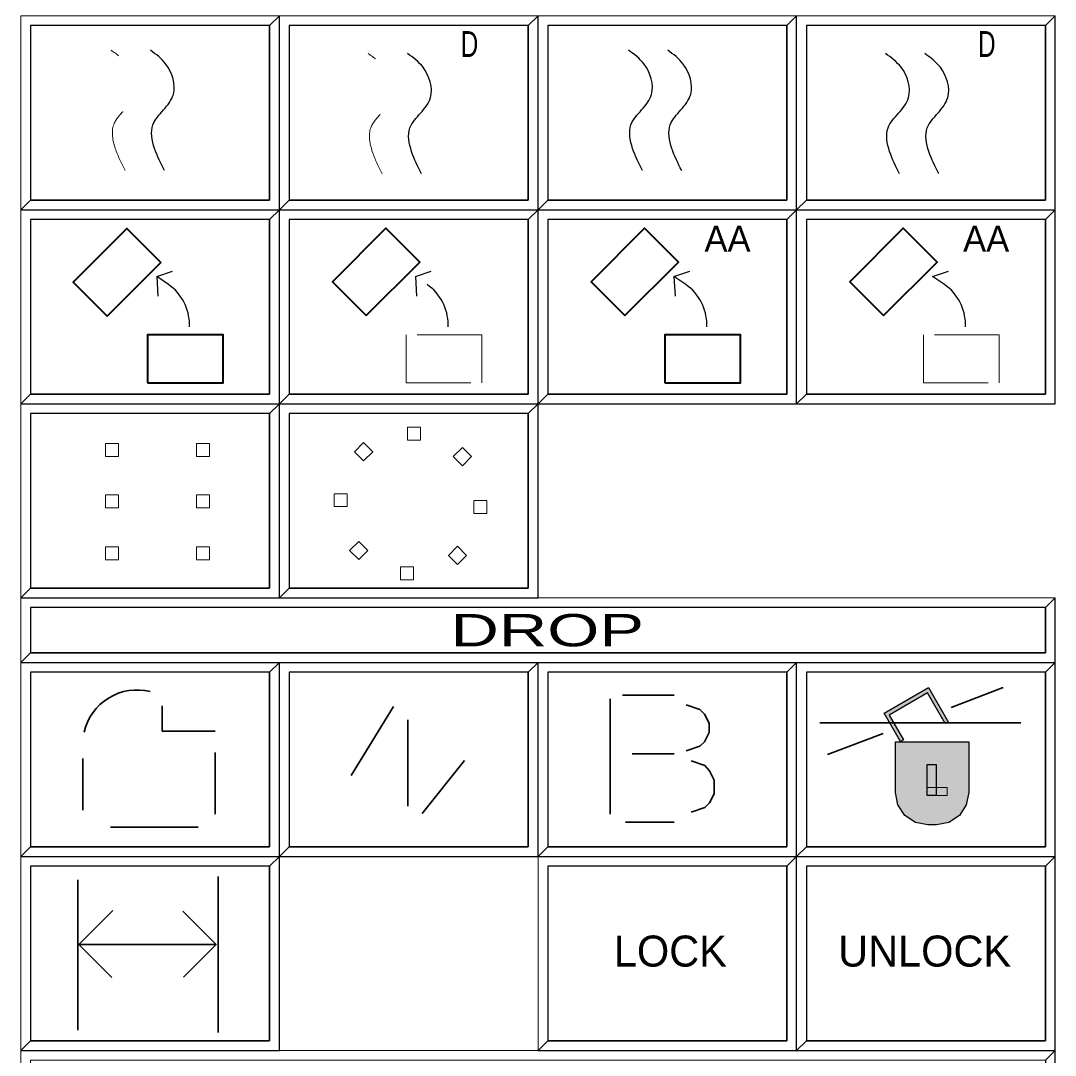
# Model space of a CAD drawing. Extents: x 95906.8 to 95923.6, y 90964.8 to 90972.8.
# Drawn here: x 95912.632 to 95914.232, y 90966.254 to 90967.854 of the extents above; entities that cross this region are included whole.
import ezdxf
from ezdxf.enums import TextEntityAlignment as Align

# ---------------------------------------------------------------- set-up
doc = ezdxf.new("R2010")
doc.units = 0
doc.header["$LTSCALE"] = 0.019
doc.linetypes.add('MEDIUM_DASHED', pattern=[4.5, 3, -1.5])
for name, color, linetype, lineweight in [('11', 7, 'Continuous', 25), ('12', 7, 'Continuous', 25), ('18', 7, 'Continuous', 25), ('2', 7, 'Continuous', 13), ('3', 7, 'Continuous', 25), ('6', 7, 'Continuous', 25), ('7', 7, 'Continuous', 35)]:
    doc.layers.add(name, color=color, linetype=linetype, lineweight=lineweight)

msp = doc.modelspace()

# ---------------------------------------------------------------- hatches: boundary and pattern name
at = {"layer": '6'}
for points in [[(95913.9928, 90966.7395), (95913.9675, 90966.7833), (95914.0361, 90966.8229), (95914.0668, 90966.7698), (95914.0621, 90966.7671), (95914.0349, 90966.8145), (95913.9753, 90966.7803), (95913.9973, 90966.7421)], [(95913.985, 90966.6604), (95913.985, 90966.7388), (95914.0985, 90966.7388), (95914.0985, 90966.6604), (95914.0947, 90966.6413), (95914.0839, 90966.625), (95914.0676, 90966.6142), (95914.0485, 90966.6104), (95914.035, 90966.6104), (95914.0159, 90966.6142), (95913.9996, 90966.625), (95913.9888, 90966.6413)], [(95914.034, 90966.7039), (95914.0482, 90966.7039), (95914.0482, 90966.6558), (95914.034, 90966.6558)], [(95914.034, 90966.6558), (95914.0653, 90966.6558), (95914.0653, 90966.6683), (95914.034, 90966.6683)]]:
    msp.add_hatch(color=256, dxfattribs=at).paths.add_polyline_path(points)

# ---------------------------------------------------------------- linework, layer by layer
at = {"layer": '11'}
for points in [[(95912.6473, 90967.5767), (95913.0173, 90967.5767), (95913.0173, 90967.8467), (95912.6473, 90967.8467)], [(95913.0473, 90967.5767), (95913.4173, 90967.5767), (95913.4173, 90967.8467), (95913.0473, 90967.8467)], [(95913.4473, 90967.5767), (95913.8173, 90967.5767), (95913.8173, 90967.8467), (95913.4473, 90967.8467)], [(95913.8473, 90967.5767), (95914.2173, 90967.5767), (95914.2173, 90967.8467), (95913.8473, 90967.8467)], [(95912.6473, 90967.2767), (95913.0173, 90967.2767), (95913.0173, 90967.5467), (95912.6473, 90967.5467)], [(95913.0473, 90967.2767), (95913.4173, 90967.2767), (95913.4173, 90967.5467), (95913.0473, 90967.5467)], [(95913.4473, 90967.2767), (95913.8173, 90967.2767), (95913.8173, 90967.5467), (95913.4473, 90967.5467)], [(95913.8473, 90967.2767), (95914.2173, 90967.2767), (95914.2173, 90967.5467), (95913.8473, 90967.5467)], [(95912.6473, 90966.9767), (95913.0173, 90966.9767), (95913.0173, 90967.2467), (95912.6473, 90967.2467)], [(95913.0473, 90966.9767), (95913.4173, 90966.9767), (95913.4173, 90967.2467), (95913.0473, 90967.2467)], [(95913.0473, 90966.5767), (95913.4173, 90966.5767), (95913.4173, 90966.8467), (95913.0473, 90966.8467)], [(95913.4473, 90966.5767), (95913.8173, 90966.5767), (95913.8173, 90966.8467), (95913.4473, 90966.8467)], [(95913.8473, 90966.5767), (95914.2173, 90966.5767), (95914.2173, 90966.8467), (95913.8473, 90966.8467)], [(95912.6473, 90966.2767), (95913.0173, 90966.2767), (95913.0173, 90966.5467), (95912.6473, 90966.5467)], [(95913.4473, 90966.2767), (95913.8173, 90966.2767), (95913.8173, 90966.5467), (95913.4473, 90966.5467)], [(95913.8473, 90966.2767), (95914.2173, 90966.2767), (95914.2173, 90966.5467), (95913.8473, 90966.5467)]]:
    msp.add_lwpolyline(points, close=True, dxfattribs=at)
at = {"layer": '12'}
msp.add_lwpolyline([(95912.6473, 90966.5767), (95913.0173, 90966.5767), (95913.0173, 90966.8467), (95912.6473, 90966.8467)], close=True, dxfattribs=at)
at = {"layer": '18'}
msp.add_lwpolyline([(95912.6473, 90966.8767), (95914.2173, 90966.8767), (95914.2173, 90966.9467), (95912.6473, 90966.9467)], close=True, dxfattribs=at)
at = {"layer": '2'}
for points in [[(95912.6323, 90967.8617), (95912.6323, 90967.5617), (95912.6473, 90967.5767), (95912.6473, 90967.8467), (95913.0173, 90967.8467), (95913.0323, 90967.8617)], [(95913.0323, 90967.8617), (95913.0323, 90967.5617), (95913.0473, 90967.5767), (95913.0473, 90967.8467), (95913.4173, 90967.8467), (95913.4323, 90967.8617)], [(95913.4323, 90967.8617), (95913.4323, 90967.5617), (95913.4473, 90967.5767), (95913.4473, 90967.8467), (95913.8173, 90967.8467), (95913.8323, 90967.8617)], [(95913.8323, 90967.8617), (95913.8323, 90967.5617), (95913.8473, 90967.5767), (95913.8473, 90967.8467), (95914.2173, 90967.8467), (95914.2323, 90967.8617)], [(95912.6323, 90967.5617), (95912.6323, 90967.2617), (95912.6473, 90967.2767), (95912.6473, 90967.5467), (95913.0173, 90967.5467), (95913.0323, 90967.5617)], [(95913.0323, 90967.5617), (95913.0323, 90967.2617), (95913.0473, 90967.2767), (95913.0473, 90967.5467), (95913.4173, 90967.5467), (95913.4323, 90967.5617)], [(95913.4323, 90967.5617), (95913.4323, 90967.2617), (95913.4473, 90967.2767), (95913.4473, 90967.5467), (95913.8173, 90967.5467), (95913.8323, 90967.5617)], [(95913.8323, 90967.5617), (95913.8323, 90967.2617), (95913.8473, 90967.2767), (95913.8473, 90967.5467), (95914.2173, 90967.5467), (95914.2323, 90967.5617)], [(95912.6323, 90967.2617), (95912.6323, 90966.9617), (95912.6473, 90966.9767), (95912.6473, 90967.2467), (95913.0173, 90967.2467), (95913.0323, 90967.2617)], [(95913.0323, 90967.2617), (95913.0323, 90966.9617), (95913.0473, 90966.9767), (95913.0473, 90967.2467), (95913.4173, 90967.2467), (95913.4323, 90967.2617)], [(95912.6323, 90966.9617), (95912.6323, 90966.8617), (95912.6473, 90966.8767), (95912.6473, 90966.9467), (95914.2173, 90966.9467), (95914.2323, 90966.9617)], [(95912.6323, 90966.8617), (95912.6323, 90966.5617), (95912.6473, 90966.5767), (95912.6473, 90966.8467), (95913.0173, 90966.8467), (95913.0323, 90966.8617)], [(95913.0323, 90966.8617), (95913.0323, 90966.5617), (95913.0473, 90966.5767), (95913.0473, 90966.8467), (95913.4173, 90966.8467), (95913.4323, 90966.8617)], [(95913.4323, 90966.8617), (95913.4323, 90966.5617), (95913.4473, 90966.5767), (95913.4473, 90966.8467), (95913.8173, 90966.8467), (95913.8323, 90966.8617)], [(95913.8323, 90966.8617), (95913.8323, 90966.5617), (95913.8473, 90966.5767), (95913.8473, 90966.8467), (95914.2173, 90966.8467), (95914.2323, 90966.8617)], [(95912.6323, 90966.5617), (95912.6323, 90966.2617), (95912.6473, 90966.2767), (95912.6473, 90966.5467), (95913.0173, 90966.5467), (95913.0323, 90966.5617)], [(95913.4323, 90966.5617), (95913.4323, 90966.2617), (95913.4473, 90966.2767), (95913.4473, 90966.5467), (95913.8173, 90966.5467), (95913.8323, 90966.5617)], [(95913.8323, 90966.5617), (95913.8323, 90966.2617), (95913.8473, 90966.2767), (95913.8473, 90966.5467), (95914.2173, 90966.5467), (95914.2323, 90966.5617)], [(95912.6323, 90966.2617), (95912.6323, 90966.1617), (95912.6473, 90966.1767), (95912.6473, 90966.2467), (95914.2173, 90966.2467), (95914.2323, 90966.2617)]]:
    msp.add_lwpolyline(points, close=True, dxfattribs=at)
at = {"layer": '3'}
for points in [[(95912.6323, 90967.5617), (95913.0323, 90967.5617), (95913.0323, 90967.8617), (95913.0173, 90967.8467), (95913.0173, 90967.5767), (95912.6473, 90967.5767)], [(95913.0323, 90967.5617), (95913.4323, 90967.5617), (95913.4323, 90967.8617), (95913.4173, 90967.8467), (95913.4173, 90967.5767), (95913.0473, 90967.5767)], [(95913.4323, 90967.5617), (95913.8323, 90967.5617), (95913.8323, 90967.8617), (95913.8173, 90967.8467), (95913.8173, 90967.5767), (95913.4473, 90967.5767)], [(95913.8323, 90967.5617), (95914.2323, 90967.5617), (95914.2323, 90967.8617), (95914.2173, 90967.8467), (95914.2173, 90967.5767), (95913.8473, 90967.5767)], [(95912.6323, 90967.2617), (95913.0323, 90967.2617), (95913.0323, 90967.5617), (95913.0173, 90967.5467), (95913.0173, 90967.2767), (95912.6473, 90967.2767)], [(95913.0323, 90967.2617), (95913.4323, 90967.2617), (95913.4323, 90967.5617), (95913.4173, 90967.5467), (95913.4173, 90967.2767), (95913.0473, 90967.2767)], [(95913.4323, 90967.2617), (95913.8323, 90967.2617), (95913.8323, 90967.5617), (95913.8173, 90967.5467), (95913.8173, 90967.2767), (95913.4473, 90967.2767)], [(95913.8323, 90967.2617), (95914.2323, 90967.2617), (95914.2323, 90967.5617), (95914.2173, 90967.5467), (95914.2173, 90967.2767), (95913.8473, 90967.2767)], [(95912.6323, 90966.9617), (95913.0323, 90966.9617), (95913.0323, 90967.2617), (95913.0173, 90967.2467), (95913.0173, 90966.9767), (95912.6473, 90966.9767)], [(95913.0323, 90966.9617), (95913.4323, 90966.9617), (95913.4323, 90967.2617), (95913.4173, 90967.2467), (95913.4173, 90966.9767), (95913.0473, 90966.9767)], [(95912.6323, 90966.8617), (95914.2323, 90966.8617), (95914.2323, 90966.9617), (95914.2173, 90966.9467), (95914.2173, 90966.8767), (95912.6473, 90966.8767)], [(95912.6323, 90966.5617), (95913.0323, 90966.5617), (95913.0323, 90966.8617), (95913.0173, 90966.8467), (95913.0173, 90966.5767), (95912.6473, 90966.5767)], [(95913.0323, 90966.5617), (95913.4323, 90966.5617), (95913.4323, 90966.8617), (95913.4173, 90966.8467), (95913.4173, 90966.5767), (95913.0473, 90966.5767)], [(95913.4323, 90966.5617), (95913.8323, 90966.5617), (95913.8323, 90966.8617), (95913.8173, 90966.8467), (95913.8173, 90966.5767), (95913.4473, 90966.5767)], [(95913.8323, 90966.5617), (95914.2323, 90966.5617), (95914.2323, 90966.8617), (95914.2173, 90966.8467), (95914.2173, 90966.5767), (95913.8473, 90966.5767)], [(95912.6323, 90966.2617), (95913.0323, 90966.2617), (95913.0323, 90966.5617), (95913.0173, 90966.5467), (95913.0173, 90966.2767), (95912.6473, 90966.2767)], [(95913.4323, 90966.2617), (95913.8323, 90966.2617), (95913.8323, 90966.5617), (95913.8173, 90966.5467), (95913.8173, 90966.2767), (95913.4473, 90966.2767)], [(95913.8323, 90966.2617), (95914.2323, 90966.2617), (95914.2323, 90966.5617), (95914.2173, 90966.5467), (95914.2173, 90966.2767), (95913.8473, 90966.2767)], [(95912.6323, 90966.1617), (95914.2323, 90966.1617), (95914.2323, 90966.2617), (95914.2173, 90966.2467), (95914.2173, 90966.1767), (95912.6473, 90966.1767)]]:
    msp.add_lwpolyline(points, close=True, dxfattribs=at)
at = {"layer": '6'}
for p, q in [((95912.8426, 90967.4585), (95912.8672, 90967.467)), ((95912.8426, 90967.4585), (95912.8442, 90967.4284)), ((95912.861, 90967.4461), (95912.8426, 90967.4585)), ((95913.2426, 90967.4585), (95913.2672, 90967.467)), ((95913.2426, 90967.4585), (95913.2442, 90967.4284)), ((95913.6426, 90967.4585), (95913.6672, 90967.467)), ((95913.6426, 90967.4585), (95913.6442, 90967.4284)), ((95913.661, 90967.4461), (95913.6426, 90967.4585)), ((95914.0426, 90967.4585), (95914.0672, 90967.467)), ((95914.061, 90967.4461), (95914.0426, 90967.4585)), ((95912.8933, 90967.381), (95912.8933, 90967.3844)), ((95913.2933, 90967.381), (95913.2933, 90967.3844)), ((95913.6933, 90967.381), (95913.6933, 90967.3844)), ((95914.0933, 90967.381), (95914.0933, 90967.3844))]:
    msp.add_line(p, q, dxfattribs=at)
at = {"layer": '6', "lineweight": 35}
for p, q in [((95914.1519, 90966.8228), (95914.0715, 90966.7921)), ((95913.5441, 90966.8053), (95913.5441, 90966.6271)), ((95913.5631, 90966.8114), (95913.643, 90966.8114)), ((95913.1434, 90966.687), (95913.2087, 90966.7935)), ((95913.231, 90966.6393), (95913.231, 90966.773)), ((95913.8683, 90966.7685), (95914.179, 90966.7685)), ((95913.8802, 90966.7192), (95913.966, 90966.7519)), ((95912.9328, 90966.7223), (95912.9328, 90966.627)), ((95913.5779, 90966.7203), (95913.643, 90966.7203)), ((95912.7284, 90966.6332), (95912.7284, 90966.7131)), ((95913.3186, 90966.71), (95913.2531, 90966.6284)), ((95913.643, 90966.6149), (95913.5677, 90966.6149)), ((95912.9067, 90966.6071), (95912.7714, 90966.6071)), ((95912.9379, 90966.5308), (95912.9379, 90966.2897)), ((95912.7206, 90966.5257), (95912.7206, 90966.2931)), ((95912.7223, 90966.4255), (95912.7747, 90966.4779)), ((95912.7223, 90966.4255), (95912.773, 90966.3747)), ((95912.9345, 90966.4255), (95912.8842, 90966.3752))]:
    msp.add_line(p, q, dxfattribs=at)
at = {"layer": '6', "lineweight": 40}
for points in [[(95912.766, 90967.3975), (95912.8488, 90967.4803), (95912.7963, 90967.5328), (95912.7135, 90967.45)], [(95913.1668, 90967.3981), (95913.2496, 90967.4809), (95913.1971, 90967.5334), (95913.1143, 90967.4506)], [(95913.5668, 90967.3981), (95913.6496, 90967.4809), (95913.5971, 90967.5334), (95913.5143, 90967.4506)], [(95913.9668, 90967.3981), (95914.0496, 90967.4809), (95913.9971, 90967.5334), (95913.9143, 90967.4506)], [(95912.8283, 90967.294), (95912.9454, 90967.294), (95912.9454, 90967.3683), (95912.8283, 90967.3683)], [(95913.6283, 90967.294), (95913.7454, 90967.294), (95913.7454, 90967.3683), (95913.6283, 90967.3683)]]:
    msp.add_lwpolyline(points, close=True, dxfattribs=at)
at = {"layer": '6', "linetype": 'MEDIUM_DASHED', "lineweight": 13}
for points in [[(95913.2283, 90967.294), (95913.3454, 90967.294), (95913.3454, 90967.3683), (95913.2283, 90967.3683)], [(95914.0283, 90967.294), (95914.1454, 90967.294), (95914.1454, 90967.3683), (95914.0283, 90967.3683)]]:
    msp.add_lwpolyline(points, close=True, dxfattribs=at)
at = {"layer": '6', "lineweight": 13}
for points in [[(95913.2305, 90967.2054), (95913.2505, 90967.2054), (95913.2505, 90967.2254), (95913.2305, 90967.2254)], [(95912.7636, 90967.1801), (95912.7836, 90967.1801), (95912.7836, 90967.2001), (95912.7636, 90967.2001)], [(95912.9043, 90967.1801), (95912.9243, 90967.1801), (95912.9243, 90967.2001), (95912.9043, 90967.2001)], [(95913.1626, 90967.1734), (95913.1767, 90967.1875), (95913.1626, 90967.2017), (95913.1485, 90967.1875)], [(95913.3012, 90967.18), (95913.3153, 90967.1659), (95913.3295, 90967.18), (95913.3153, 90967.1941)], [(95912.7636, 90967.101), (95912.7836, 90967.101), (95912.7836, 90967.121), (95912.7636, 90967.121)], [(95912.9043, 90967.101), (95912.9243, 90967.101), (95912.9243, 90967.121), (95912.9043, 90967.121)], [(95913.1372, 90967.1027), (95913.1372, 90967.1227), (95913.1172, 90967.1227), (95913.1172, 90967.1027)], [(95913.3332, 90967.1121), (95913.3332, 90967.0921), (95913.3532, 90967.0921), (95913.3532, 90967.1121)], [(95912.7636, 90967.0204), (95912.7836, 90967.0204), (95912.7836, 90967.0404), (95912.7636, 90967.0404)], [(95912.9043, 90967.0204), (95912.9243, 90967.0204), (95912.9243, 90967.0404), (95912.9043, 90967.0404)], [(95913.1692, 90967.0348), (95913.1551, 90967.0489), (95913.1409, 90967.0348), (95913.1551, 90967.0207)], [(95913.3078, 90967.0414), (95913.2937, 90967.0273), (95913.3078, 90967.0131), (95913.3219, 90967.0273)], [(95913.2399, 90967.0094), (95913.2199, 90967.0094), (95913.2199, 90966.9894), (95913.2399, 90966.9894)], [(95914.034, 90966.6558), (95914.0653, 90966.6558), (95914.0653, 90966.6683), (95914.034, 90966.6683)]]:
    msp.add_lwpolyline(points, close=True, dxfattribs=at)
at = {"layer": '6'}
for points in [[(95913.9928, 90966.7395), (95913.9675, 90966.7833), (95914.0361, 90966.8229), (95914.0668, 90966.7698), (95914.0621, 90966.7671), (95914.0349, 90966.8145), (95913.9753, 90966.7803), (95913.9973, 90966.7421)], [(95913.985, 90966.6604), (95913.985, 90966.7388), (95914.0985, 90966.7388), (95914.0985, 90966.6604), (95914.0947, 90966.6413), (95914.0839, 90966.625), (95914.0676, 90966.6142), (95914.0485, 90966.6104), (95914.035, 90966.6104), (95914.0159, 90966.6142), (95913.9996, 90966.625), (95913.9888, 90966.6413)], [(95914.034, 90966.7039), (95914.0482, 90966.7039), (95914.0482, 90966.6558), (95914.034, 90966.6558)]]:
    msp.add_lwpolyline(points, close=True, dxfattribs=at)
at = {"layer": '6', "lineweight": 35}
for points in [[(95912.9328, 90966.7557), (95912.8513, 90966.7557), (95912.8513, 90966.7946)], [(95913.6614, 90966.796), (95913.6828, 90966.7889), (95913.6899, 90966.7818), (95913.697, 90966.7676), (95913.697, 90966.7534), (95913.6899, 90966.7392), (95913.6828, 90966.7321), (95913.6614, 90966.7249)], [(95913.6691, 90966.7095), (95913.6905, 90966.7024), (95913.6976, 90966.6941), (95913.7047, 90966.6799), (95913.7047, 90966.6586), (95913.6976, 90966.6444), (95913.6905, 90966.6373), (95913.6691, 90966.6302)], [(95912.7223, 90966.4255), (95912.9345, 90966.4255), (95912.883, 90966.477)]]:
    msp.add_lwpolyline(points, dxfattribs=at)
at = {"layer": '6'}
for centre in [(95912.8183, 90967.3844), (95913.2183, 90967.3844), (95913.6183, 90967.3844), (95914.0183, 90967.3844)]:
    msp.add_arc(centre, 0.075, 0, 55.2568, dxfattribs=at)
at = {"layer": '6', "lineweight": 35}
msp.add_arc((95912.8121, 90966.7354), 0.0838, 75.8303, 167.4043, dxfattribs=at)
at = {"layer": '6', "linetype": 'MEDIUM_DASHED', "lineweight": 13}
for points in [[(95912.7938, 90967.6226), (95912.7786, 90967.6568), (95912.7761, 90967.6934), (95912.7925, 90967.7162), (95912.8077, 90967.7402), (95912.7963, 90967.7871), (95912.7722, 90967.8085)], [(95913.1913, 90967.6176), (95913.1761, 90967.6518), (95913.1736, 90967.6884), (95913.19, 90967.7112), (95913.2052, 90967.7352), (95913.1938, 90967.7821), (95913.1697, 90967.8035)]]:
    msp.add_spline(points, degree=3, dxfattribs=at)
at = {"layer": '6'}
for points in [[(95912.8545, 90967.6226), (95912.8393, 90967.6568), (95912.8368, 90967.6934), (95912.8532, 90967.7162), (95912.8684, 90967.7402), (95912.857, 90967.7871), (95912.833, 90967.8085)], [(95913.5938, 90967.6226), (95913.5786, 90967.6568), (95913.5761, 90967.6934), (95913.5925, 90967.7162), (95913.6077, 90967.7402), (95913.5963, 90967.7871), (95913.5722, 90967.8085)], [(95913.6545, 90967.6226), (95913.6393, 90967.6568), (95913.6368, 90967.6934), (95913.6532, 90967.7162), (95913.6684, 90967.7402), (95913.657, 90967.7871), (95913.633, 90967.8085)], [(95913.252, 90967.6176), (95913.2368, 90967.6518), (95913.2343, 90967.6884), (95913.2507, 90967.7112), (95913.2659, 90967.7352), (95913.2545, 90967.7821), (95913.2305, 90967.8035)], [(95913.9913, 90967.6176), (95913.9761, 90967.6518), (95913.9736, 90967.6884), (95913.99, 90967.7112), (95914.0052, 90967.7352), (95913.9938, 90967.7821), (95913.9697, 90967.8035)], [(95914.052, 90967.6176), (95914.0368, 90967.6518), (95914.0343, 90967.6884), (95914.0507, 90967.7112), (95914.0659, 90967.7352), (95914.0545, 90967.7821), (95914.0305, 90967.8035)]]:
    msp.add_spline(points, degree=3, dxfattribs=at)

# ---------------------------------------------------------------- texts
at = {"layer": '6', "width": 0.7}
for p in [(95913.3264, 90967.7981), (95914.1264, 90967.7981)]:
    msp.add_text('D', height=0.04, dxfattribs=at).set_placement(p, align=Align.CENTER)
at = {"layer": '6'}
for s, height, p in [('AA', 0.04, (95913.7254, 90967.497)), ('AA', 0.04, (95914.1254, 90967.497)), ('LOCK', 0.048, (95913.637, 90966.3914)), ('UNLOCK', 0.048, (95914.0302, 90966.3914))]:
    msp.add_text(s, height=height, dxfattribs=at).set_placement(p, align=Align.CENTER)
at = {"layer": '7', "width": 1.55}
msp.add_text('          DROP         ', height=0.04999, dxfattribs=at).set_placement((95913.4322, 90966.8867), align=Align.CENTER)

doc.saveas('drawing.dxf')
